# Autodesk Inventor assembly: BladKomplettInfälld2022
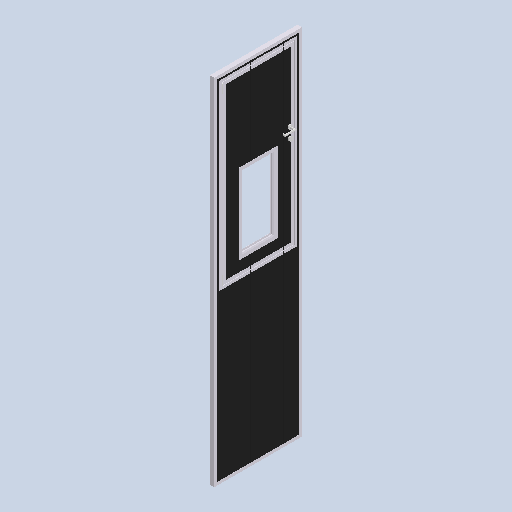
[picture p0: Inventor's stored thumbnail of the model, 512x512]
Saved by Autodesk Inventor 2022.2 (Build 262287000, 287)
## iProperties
Created: 2022-02
Part Number: BladKomplettInfälld2022
Document SubType Name: Assembly
Designer: cl
Author: cl
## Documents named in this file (8)
- G:\AutoCad\Carl Lund\3D-modeller systemlösningar\3D-modell-systemlösning-2022\Parts\BladKomplettInfälld2022.iam
- G:\AutoCad\Carl Lund\3D-modeller systemlösningar\3D-modell-systemlösning-2022\Styrande.iam
- G:\AutoCad\Carl Lund\3D-modeller systemlösningar\3D-modell-systemlösning-2022\Parts\AluKarmBlad.ipt
- G:\AutoCad\Carl Lund\3D-modeller systemlösningar\3D-modell-systemlösning-2022\Parts\BladInfäld.ipt
- G:\AutoCad\Carl Lund\3D-modeller systemlösningar\3D-modell-systemlösning-2022\Parts\Fönsterkarm.ipt
- G:\AutoCad\Carl Lund\3D-modeller systemlösningar\3D-modell-systemlösning-2022\Parts\InfälldGångDörrAlu.ipt
- G:\AutoCad\Carl Lund\3D-modeller systemlösningar\3D-modell-systemlösning-2022\Parts\DörrHAndtag-V.ipt
- G:\AutoCad\Carl Lund\3D-modeller systemlösningar\3D-modell-systemlösning-2022\Parts\GångJärnInf.ipt
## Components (8 placed, 6 different names)
1. BladInfäld:1 — Mate:1, Mate:2, Flush:1, Mate:3, Flush:2, Flush:3, Mate:4
2. AluKarmBlad:1 — Mate:3, Flush:2, Flush:3, Flush:6, Flush:7, Flush:11, Flush:12, Mate:5, Mate:7, Mate:11, Mate:14, Mate:15, Mate:16
3. Fönsterkarm:1 — Mate:4, Flush:6, Flush:7, Flush:8, Flush:9, Flush:10
4. Fönsterkarm:2 — Flush:8, Flush:9, Flush:10
5. InfälldGångDörrAlu:1 — Flush:11, Flush:12, Mate:5, Flush:13, Flush:14, Mate:12, Mate:13
6. DörrHAndtag-V:1 — Mate:7, Mate:13, Mate:14, Mate:15, Mate:16
7. GångJärnInf:1 — Flush:13, Mate:10, Mate:11, Mate:12
8. GångJärnInf:2 — Mate:10, Flush:14
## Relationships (25: Mate 13, Flush 12)
- Mate:1: BladInfäld:1
- Mate:2: BladInfäld:1
- Flush:1: BladInfäld:1
- Mate:3: BladInfäld:1 ↔ AluKarmBlad:1
- Flush:2: BladInfäld:1 ↔ AluKarmBlad:1
- Flush:3: BladInfäld:1 ↔ AluKarmBlad:1
- Mate:4: BladInfäld:1 ↔ Fönsterkarm:1
- Flush:6: AluKarmBlad:1 ↔ Fönsterkarm:1
- Flush:7: AluKarmBlad:1 ↔ Fönsterkarm:1
- Flush:8: Fönsterkarm:1 ↔ Fönsterkarm:2
- Flush:9: Fönsterkarm:1 ↔ Fönsterkarm:2
- Flush:10: Fönsterkarm:1 ↔ Fönsterkarm:2
- Flush:11: AluKarmBlad:1 ↔ InfälldGångDörrAlu:1
- Flush:12: AluKarmBlad:1 ↔ InfälldGångDörrAlu:1
- Mate:5: AluKarmBlad:1 ↔ InfälldGångDörrAlu:1
- Mate:7: AluKarmBlad:1 ↔ DörrHAndtag-V:1
- Flush:13: InfälldGångDörrAlu:1 ↔ GångJärnInf:1
- Mate:10: GångJärnInf:1 ↔ GångJärnInf:2
- Flush:14: InfälldGångDörrAlu:1 ↔ GångJärnInf:2
- Mate:11: AluKarmBlad:1 ↔ GångJärnInf:1
- Mate:12: InfälldGångDörrAlu:1 ↔ GångJärnInf:1
- Mate:13: InfälldGångDörrAlu:1 ↔ DörrHAndtag-V:1
- Mate:14: AluKarmBlad:1 ↔ DörrHAndtag-V:1
- Mate:15: AluKarmBlad:1 ↔ DörrHAndtag-V:1
- Mate:16: AluKarmBlad:1 ↔ DörrHAndtag-V:1
## Named parameters: BladBredd = 987.5 mm, Fönsterhöjd = 862 mm, Blad2 = 1012.5 mm, Blad3 = 0, Blad4 = 0, Blad5 = 1012.5 mm, Blad6 = 2025 mm, MGJ12Djup = 0, MGJ12Bredd = 0, MGJ2Djup = 0, MGJ2Bredd = 5012.5 mm, MGJ56Djup = 0, MGJ56Bredd = 0, MGJ23Djup = 48 mm, MGJ45Djup = 48 mm, GarageRegel5 = 0, GarageRegel6 = 0, Styrrulle2Djup = 0, FönsterhöjdStyrning = 862 mm, FönsterKarm = 54 mm, AndraGlasraden = 0, BrösthöjdStyrning2 = 0.0001 mm, InfälldGångDörr = 0, Infälldstyr = 845.83333 mm
